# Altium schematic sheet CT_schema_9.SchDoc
size 277 x 170 mm
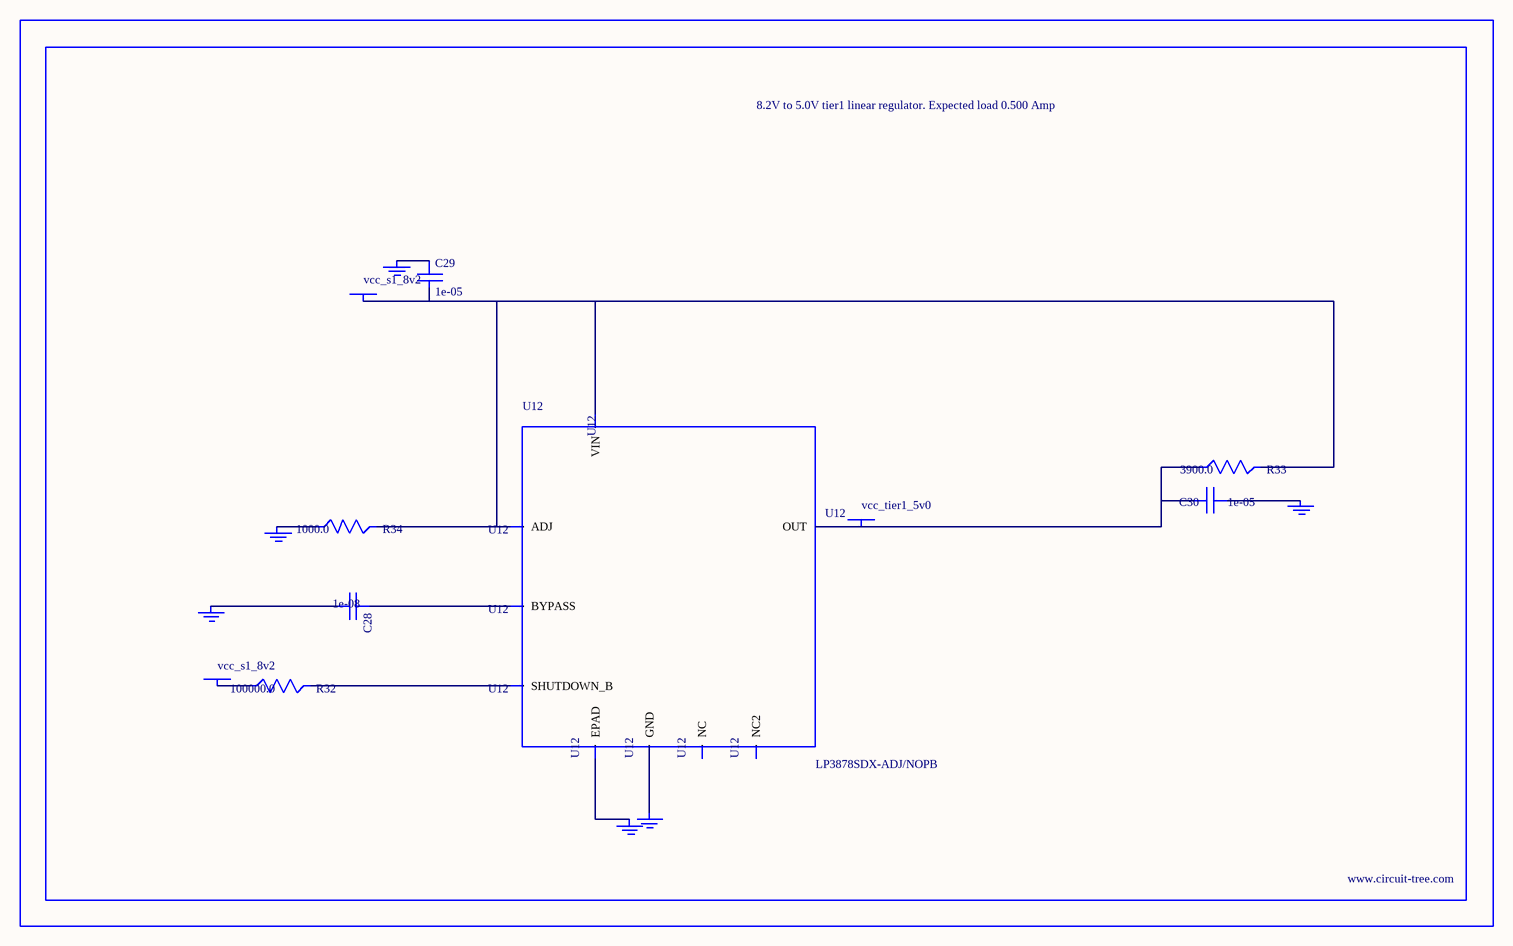
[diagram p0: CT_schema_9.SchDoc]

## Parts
BORDER8  (no value)
C28  1e-08  [C0402]
C29  1e-05  [C1206]
C30  1e-05  [C1210]
GND_INSTANCE_8_0  (no value)
GND_INSTANCE_8_1  (no value)
GND_INSTANCE_8_2  (no value)
GND_INSTANCE_8_3  (no value)
GND_INSTANCE_8_4  (no value)
GND_INSTANCE_8_5  (no value)
POWER_INSTANCE_8_0  vcc_s1_8v2
POWER_INSTANCE_8_1  vcc_s1_8v2
POWER_INSTANCE_8_2  vcc_tier1_5v0
R32  100000.0  [R0603]
R33  3900.0  [R0603]
R34  1000.0  [R0603]
U12  LP3878SDX-ADJ/NOPB  [WSON-8]

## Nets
NetC28_1: C28.1 U12.1(BYPASS)
NetC28_2: C28.2 GND_INSTANCE_8_0.0(GND)
NetC29_1: C29.1 GND_INSTANCE_8_1.0(GND)
NetC29_2: C29.2 POWER_INSTANCE_8_0.0(PWR) R33.2 R34.2 U12.4(VIN) U12.6(ADJ)
NetC30_1: C30.1 GND_INSTANCE_8_2.0(GND)
NetC30_2: C30.2 POWER_INSTANCE_8_2.0(PWR) R33.1 U12.5(OUT)
NetGND_INSTANCE_8_3_0: GND_INSTANCE_8_3.0(GND) R34.1
NetGND_INSTANCE_8_4_0: GND_INSTANCE_8_4.0(GND) U12.PAD(EPAD)
NetGND_INSTANCE_8_5_0: GND_INSTANCE_8_5.0(GND) U12.3(GND)
NetPOWER_INSTANCE_8_1_0: POWER_INSTANCE_8_1.0(PWR) R32.1
NetR32_2: R32.2 U12.8(SHUTDOWN_B)

Not connected (* = marked no-connect by the designer): U12 2(NC) 7(NC2)

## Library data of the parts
BORDER8 = BORDER_PAGE8
C28 = C0402C103K3RAC
C29 = C1206C106K3RACTU
C30 = GRM32DR61E106MA12L
GND_INSTANCE_8_0-GND_INSTANCE_8_5 = GND
POWER_INSTANCE_8_0-POWER_INSTANCE_8_2 = PWR
R32 = RC0603JR-07100KL
R33 = RC0603JR-073K9L
R34 = RC0603JR-071KL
